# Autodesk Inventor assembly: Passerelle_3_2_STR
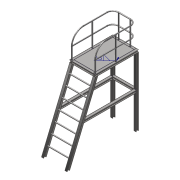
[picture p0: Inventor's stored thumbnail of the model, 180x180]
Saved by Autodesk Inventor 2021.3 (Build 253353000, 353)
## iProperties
_SolveAssemblyDoc: Frame Generator Solve Assembly
_Version: 25.0.0
Created: 2018-07
Part Number: Passerelle_3_2_STR
Material: Générique
Document SubType Name: Construction soudée
Designer: Fabian Perrée
Weld Material: Aluminium 6061, soudé
Mass: 516856 g
Surface Area: 471768 cm^2
Volume: 7.19753e+06 cm^3
Density: 0.0718102 g/cm^3
Author: Fabian Perrée
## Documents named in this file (4)
- C:\Users\Fabian\Google Drive\04_CAO-DAO\01_Exercices\01_Inventor\01_Fichiers_exercice_Inventor\01_Definitif\Frame Generator\Passerelle_3_2_STR.iam
- C:\Users\Fabian\Google Drive\04_CAO-DAO\01_Exercices\01_Inventor\01_Fichiers_exercice_Inventor\01_Definitif\Frame Generator\Passerelle_2_3_Sque_STR.ipt
- C:\Users\Fabian\Google Drive\04_CAO-DAO\01_Exercices\01_Inventor\01_Fichiers_exercice_Inventor\01_Definitif\Frame Generator\Frame\Frame0001.iam
- C:\Users\Fabian\Google Drive\04_CAO-DAO\01_Exercices\01_Inventor\01_Fichiers_exercice_Inventor\01_Definitif\Frame Generator\Plateforme_3_2_STR.ipt
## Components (3 placed, 3 different names)
1. Passerelle_2_3_Sque_STR:1 — Affleurement:1, Affleurement:2
2. Frame0001:1 [sub-assembly]
3. Plateforme_3_2_STR:1 — Affleurement:1, Affleurement:2
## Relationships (2: Flush 2)
- Affleurement:1 [Flush]: Passerelle_2_3_Sque_STR:1 ↔ Plateforme_3_2_STR:1
- Affleurement:2 [Flush]: Passerelle_2_3_Sque_STR:1 ↔ Plateforme_3_2_STR:1
